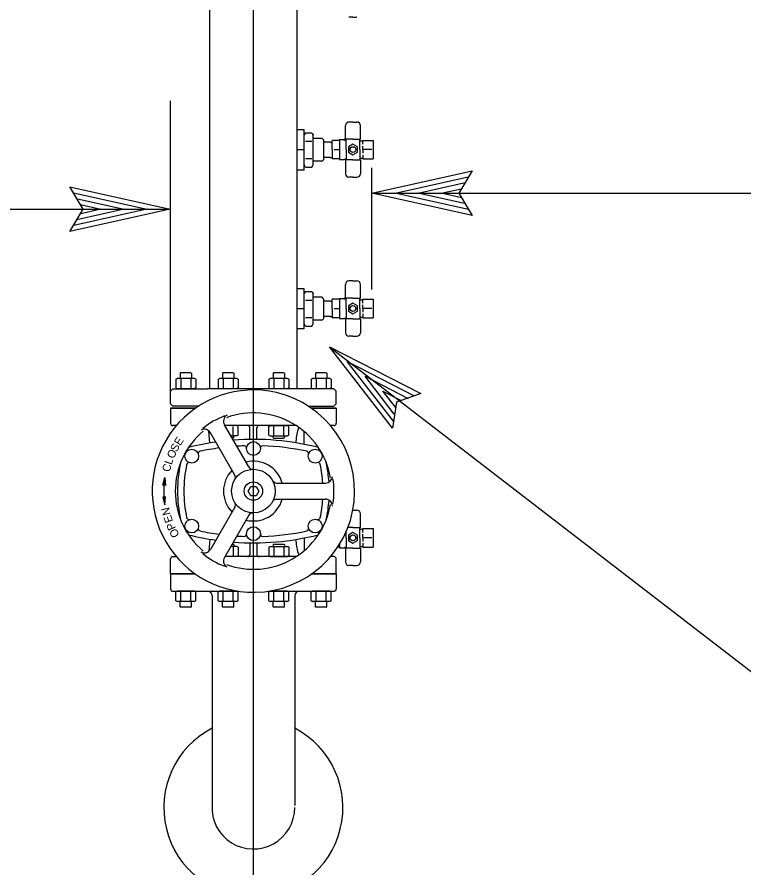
# Model space of a CAD drawing. Extents: x -1680 to 1155, y -802 to 799.
# Drawn here: x 469.8 to 513.3, y -472.5 to -421.5 of the extents above; entities that cross this region are included whole.
import ezdxf

# ---------------------------------------------------------------- set-up
doc = ezdxf.new("R2010")
doc.units = 0
doc.layers.add('Misc CnstDet(22)', color=7, linetype='Continuous')

msp = doc.modelspace()

# ---------------------------------------------------------------- linework, layer by layer
at = {"layer": 'Misc CnstDet(22)'}
for p, q in [((483.911, -491.28), (483.911, -367.568)), ((481.299, -443.793), (481.299, -415.653)), ((486.531, -443.793), (486.531, -415.653)), ((489.873, -421.544), (489.634, -421.544)), ((489.873, -421.544), (490.113, -421.544)), ((478.959, -444.309), (478.959, -426.565)), ((486.944, -428.293), (486.531, -428.293)), ((486.944, -430.702), (486.944, -428.293)), ((489.427, -428.86), (489.427, -428.034)), ((489.873, -427.828), (489.634, -427.828)), ((489.873, -427.828), (490.113, -427.828)), ((490.319, -428.86), (490.319, -428.034)), ((487.024, -428.469), (486.944, -428.608)), ((487.024, -428.469), (487.414, -428.469)), ((487.414, -428.469), (487.494, -428.608)), ((487.457, -428.534), (487.494, -428.599)), ((487.494, -430.388), (487.494, -428.599)), ((487.494, -430.388), (487.494, -428.599)), ((488.029, -428.805), (487.494, -428.806)), ((488.138, -428.915), (488.029, -428.805)), ((487.026, -428.977), (487.412, -428.977)), ((488.138, -430.071), (488.138, -428.915)), ((488.242, -429.031), (488.138, -429.034)), ((488.517, -429.031), (488.242, -429.031)), ((488.517, -429.031), (488.62, -429.034)), ((488.621, -429.48), (488.621, -428.929)), ((489.072, -428.929), (488.621, -428.929)), ((488.676, -429.084), (488.676, -429.084)), ((489.072, -428.929), (489.002, -428.929)), ((489.072, -428.879), (489.072, -430.08)), ((489.072, -428.879), (489.348, -428.879)), ((489.372, -428.879), (489.372, -428.879)), ((489.372, -428.929), (489.372, -428.896)), ((489.391, -428.905), (489.46, -428.905)), ((489.873, -428.86), (489.427, -428.86)), ((489.46, -429.48), (489.46, -428.86)), ((489.873, -428.86), (490.319, -428.86)), ((490.286, -429.48), (490.286, -428.86)), ((490.291, -428.963), (490.449, -428.963)), ((490.466, -429.154), (490.466, -428.929)), ((490.466, -428.929), (491.075, -428.929)), ((490.466, -429.48), (490.466, -429.267)), ((491.075, -428.929), (491.075, -429.48)), ((486.944, -429.498), (486.531, -429.498)), ((488.621, -429.48), (488.621, -430.03)), ((488.746, -429.48), (489.072, -429.48)), ((489.46, -429.48), (489.46, -430.099)), ((490.286, -429.48), (490.286, -430.099)), ((490.466, -429.48), (490.466, -429.693)), ((490.466, -429.805), (490.466, -430.03)), ((491.011, -429.48), (490.53, -429.48)), ((491.075, -429.48), (491.075, -430.03)), ((487.026, -430.01), (487.412, -430.01)), ((488.029, -430.181), (487.494, -430.181)), ((488.138, -430.071), (488.029, -430.181)), ((488.242, -429.956), (488.138, -429.953)), ((488.517, -429.956), (488.242, -429.956)), ((488.517, -429.956), (488.62, -429.953)), ((489.072, -430.03), (488.621, -430.03)), ((488.676, -430.009), (488.676, -430.009)), ((489.072, -430.08), (489.348, -430.08)), ((489.372, -430.03), (489.372, -430.063)), ((489.391, -430.054), (489.46, -430.054)), ((489.427, -430.099), (489.427, -430.925)), ((489.873, -430.099), (489.427, -430.099)), ((489.873, -430.099), (490.319, -430.099)), ((490.291, -429.996), (490.449, -429.996)), ((490.319, -430.099), (490.319, -430.925)), ((490.466, -430.03), (491.075, -430.03)), ((486.944, -430.702), (486.531, -430.702)), ((487.024, -430.526), (486.944, -430.388)), ((487.024, -430.526), (487.414, -430.526)), ((487.414, -430.526), (487.494, -430.388)), ((490.999, -437.861), (490.999, -430.566)), ((490.999, -432.082), (496.999, -430.752)), ((496.999, -430.752), (496.199, -432.082)), ((496.999, -430.752), (496.999, -430.752)), ((489.873, -431.132), (489.634, -431.132)), ((489.873, -431.132), (490.113, -431.132)), ((492.39, -432.079), (496.764, -431.112)), ((473.733, -433.05), (472.933, -431.71)), ((472.933, -431.71), (472.933, -431.71)), ((472.933, -431.71), (478.933, -433.05)), ((493.762, -432.085), (496.587, -431.458)), ((495.143, -432.086), (496.352, -431.818)), ((473.149, -432.066), (477.553, -433.049)), ((496.999, -433.422), (490.999, -432.082)), ((490.999, -432.082), (490.999, -432.082)), ((490.999, -432.082), (565.927, -432.083)), ((496.783, -433.067), (492.379, -432.083)), ((496.549, -432.707), (493.762, -432.085)), ((496.373, -432.36), (495.143, -432.086)), ((496.199, -432.082), (496.999, -433.422)), ((473.383, -432.425), (476.17, -433.048)), ((473.559, -432.772), (474.788, -433.047)), ((415.24, -433.05), (478.933, -433.05)), ((478.933, -433.05), (472.932, -434.38)), ((472.933, -434.38), (473.733, -433.05)), ((477.542, -433.053), (473.167, -434.021)), ((476.17, -433.048), (473.345, -433.674)), ((474.788, -433.047), (473.58, -433.315)), ((478.933, -433.05), (478.933, -433.05)), ((496.999, -433.422), (496.999, -433.422)), ((472.933, -434.38), (472.933, -434.38)), ((489.873, -437.338), (489.634, -437.338)), ((489.873, -437.338), (490.113, -437.338)), ((486.944, -437.804), (486.531, -437.804)), ((486.944, -440.213), (486.944, -437.804)), ((487.024, -437.979), (486.944, -438.118)), ((487.024, -437.979), (487.414, -437.979)), ((487.414, -437.979), (487.494, -438.118)), ((489.427, -438.371), (489.427, -437.545)), ((490.319, -438.371), (490.319, -437.545)), ((487.026, -438.487), (487.412, -438.487)), ((487.457, -438.045), (487.494, -438.109)), ((487.494, -439.898), (487.494, -438.109)), ((487.494, -439.898), (487.494, -438.109)), ((488.029, -438.316), (487.494, -438.316)), ((488.138, -438.425), (488.029, -438.316)), ((488.138, -439.582), (488.138, -438.425)), ((488.621, -438.99), (488.621, -438.439)), ((489.072, -438.439), (488.621, -438.439)), ((489.072, -438.439), (489.002, -438.439)), ((489.072, -438.389), (489.072, -439.591)), ((489.072, -438.389), (489.348, -438.389)), ((489.372, -438.389), (489.372, -438.389)), ((489.372, -438.439), (489.372, -438.406)), ((489.391, -438.415), (489.46, -438.415)), ((489.873, -438.371), (489.427, -438.371)), ((489.46, -438.99), (489.46, -438.371)), ((489.873, -438.371), (490.319, -438.371)), ((490.286, -438.99), (490.286, -438.371)), ((490.291, -438.474), (490.449, -438.474)), ((490.466, -438.665), (490.466, -438.439)), ((490.466, -438.439), (491.075, -438.439)), ((491.075, -438.439), (491.075, -438.99)), ((486.944, -439.008), (486.531, -439.008)), ((488.242, -438.541), (488.138, -438.544)), ((488.517, -438.541), (488.242, -438.541)), ((488.517, -438.541), (488.62, -438.544)), ((488.621, -438.99), (488.621, -439.541)), ((488.676, -438.594), (488.676, -438.594)), ((488.746, -438.99), (489.072, -438.99)), ((489.46, -438.99), (489.46, -439.61)), ((490.286, -438.99), (490.286, -439.61)), ((490.466, -438.99), (490.466, -438.777)), ((490.466, -438.99), (490.466, -439.203)), ((491.011, -438.99), (490.53, -438.99)), ((491.075, -438.99), (491.075, -439.541)), ((487.026, -439.52), (487.412, -439.52)), ((488.242, -439.466), (488.138, -439.463)), ((488.517, -439.466), (488.242, -439.466)), ((488.517, -439.466), (488.62, -439.463)), ((488.676, -439.519), (488.676, -439.519)), ((490.291, -439.506), (490.449, -439.506)), ((490.466, -439.315), (490.466, -439.541)), ((487.024, -440.037), (486.944, -439.898)), ((487.024, -440.037), (487.414, -440.037)), ((487.414, -440.037), (487.494, -439.898)), ((488.029, -439.691), (487.494, -439.691)), ((488.138, -439.582), (488.029, -439.691)), ((489.072, -439.541), (488.621, -439.541)), ((489.072, -439.591), (489.348, -439.591)), ((489.372, -439.541), (489.372, -439.574)), ((489.391, -439.565), (489.46, -439.565)), ((489.427, -439.61), (489.427, -440.436)), ((489.873, -439.61), (489.427, -439.61)), ((489.873, -439.61), (490.319, -439.61)), ((490.319, -439.61), (490.319, -440.436)), ((490.466, -439.541), (491.075, -439.541)), ((486.944, -440.213), (486.531, -440.213)), ((489.873, -440.642), (489.634, -440.642)), ((489.873, -440.642), (490.113, -440.642)), ((492.235, -446.142), (488.465, -441.286)), ((488.465, -441.286), (488.465, -441.286)), ((488.465, -441.286), (493.936, -444.085)), ((492.295, -445.73), (489.528, -442.166)), ((489.539, -442.17), (493.526, -444.212)), ((479.555, -442.83), (479.522, -442.863)), ((479.522, -442.863), (479.522, -443.176)), ((480.177, -442.83), (479.555, -442.83)), ((480.177, -442.83), (480.21, -442.863)), ((480.21, -442.863), (480.21, -443.176)), ((482.088, -442.83), (482.055, -442.863)), ((482.055, -442.863), (482.055, -443.176)), ((482.71, -442.83), (482.088, -442.83)), ((482.71, -442.83), (482.743, -442.863)), ((482.743, -442.863), (482.743, -443.176)), ((485.12, -442.83), (485.087, -442.863)), ((485.087, -442.863), (485.087, -443.176)), ((485.742, -442.83), (485.12, -442.83)), ((485.742, -442.83), (485.775, -442.863)), ((485.775, -442.863), (485.775, -443.176)), ((487.653, -442.83), (487.62, -442.863)), ((487.62, -442.863), (487.62, -443.176)), ((488.275, -442.83), (487.653, -442.83)), ((488.275, -442.83), (488.308, -442.863)), ((488.308, -442.863), (488.308, -443.176)), ((492.344, -445.304), (490.593, -443.048)), ((490.593, -443.048), (493.169, -444.366)), ((479.27, -443.223), (479.35, -443.176)), ((479.27, -443.223), (479.27, -443.747)), ((480.382, -443.176), (479.35, -443.176)), ((479.568, -443.224), (479.568, -443.746)), ((480.164, -443.224), (480.164, -443.746)), ((480.462, -443.223), (480.382, -443.176)), ((480.462, -443.223), (480.462, -443.747)), ((481.803, -443.223), (481.883, -443.176)), ((481.803, -443.223), (481.803, -443.747)), ((482.915, -443.176), (481.883, -443.176)), ((482.101, -443.224), (482.101, -443.746)), ((482.697, -443.224), (482.697, -443.746)), ((482.995, -443.223), (482.915, -443.176)), ((482.995, -443.223), (482.995, -443.747)), ((484.835, -443.223), (484.915, -443.176)), ((484.835, -443.223), (484.835, -443.747)), ((485.947, -443.176), (484.915, -443.176)), ((485.133, -443.224), (485.133, -443.746)), ((485.729, -443.224), (485.729, -443.746)), ((486.027, -443.223), (485.947, -443.176)), ((486.027, -443.223), (486.027, -443.747)), ((487.368, -443.223), (487.448, -443.176)), ((487.368, -443.223), (487.368, -443.747)), ((488.48, -443.176), (487.448, -443.176)), ((487.666, -443.224), (487.666, -443.746)), ((488.262, -443.224), (488.262, -443.746)), ((488.56, -443.223), (488.48, -443.176)), ((488.56, -443.223), (488.56, -443.747)), ((478.959, -443.931), (479.097, -443.793)), ((478.959, -444.688), (478.959, -443.931)), ((479.097, -443.793), (481.162, -443.793)), ((479.27, -443.747), (479.35, -443.793)), ((480.382, -443.793), (479.35, -443.793)), ((480.462, -443.747), (480.382, -443.793)), ((488.733, -443.793), (481.162, -443.793)), ((481.803, -443.747), (481.883, -443.793)), ((482.915, -443.793), (481.883, -443.793)), ((482.995, -443.747), (482.915, -443.793)), ((484.835, -443.747), (484.915, -443.793)), ((485.947, -443.793), (484.915, -443.793)), ((486.027, -443.747), (485.947, -443.793)), ((487.368, -443.747), (487.448, -443.793)), ((488.48, -443.793), (487.448, -443.793)), ((488.56, -443.747), (488.48, -443.793)), ((488.871, -443.931), (488.733, -443.793)), ((488.871, -444.688), (488.871, -443.931)), ((492.429, -444.924), (491.656, -443.929)), ((491.656, -443.929), (492.759, -444.493)), ((493.936, -444.085), (492.472, -444.6)), ((493.936, -444.085), (493.936, -444.085)), ((492.472, -444.6), (492.235, -446.142)), ((478.959, -444.688), (479.097, -444.826)), ((480.432, -444.963), (478.959, -444.963)), ((478.959, -444.963), (478.959, -445.858)), ((478.959, -444.963), (480.432, -444.963)), ((478.959, -444.963), (480.432, -444.963)), ((480.637, -444.826), (479.097, -444.826)), ((487.193, -444.826), (488.733, -444.826)), ((488.871, -444.963), (487.398, -444.963)), ((487.398, -444.963), (488.871, -444.963)), ((487.398, -444.963), (488.871, -444.963)), ((488.733, -444.826), (488.871, -444.688)), ((488.871, -444.963), (488.871, -445.858)), ((479.3, -445.996), (479.097, -445.996)), ((483.637, -448.474), (482.176, -445.943)), ((486.467, -445.996), (482.206, -445.996)), ((482.915, -445.996), (482.206, -445.996)), ((482.697, -446.565), (482.697, -446.043)), ((482.995, -446.042), (482.915, -445.996)), ((482.995, -446.566), (482.995, -446.042)), ((483.709, -446.823), (483.709, -446.133)), ((484.122, -446.823), (484.122, -446.133)), ((484.835, -446.042), (484.915, -445.996)), ((484.835, -446.566), (484.835, -446.042)), ((484.915, -445.996), (485.947, -445.996)), ((485.133, -446.565), (485.133, -446.043)), ((485.729, -446.565), (485.729, -446.043)), ((486.027, -446.042), (485.947, -445.996)), ((486.027, -446.566), (486.027, -446.042)), ((488.733, -445.996), (488.53, -445.996)), ((492.235, -446.142), (492.235, -446.142)), ((481.304, -447.04), (481.253, -446.318)), ((482.803, -448.956), (481.341, -446.425)), ((482.915, -446.612), (482.562, -446.612)), ((482.743, -446.717), (482.743, -446.612)), ((482.995, -446.566), (482.915, -446.612)), ((484.835, -446.566), (484.915, -446.612)), ((484.915, -446.612), (485.947, -446.612)), ((485.087, -446.717), (485.087, -446.612)), ((485.775, -446.717), (485.775, -446.612)), ((486.027, -446.566), (485.947, -446.612)), ((486.944, -447.115), (486.944, -446.35)), ((482.743, -446.717), (482.623, -446.717)), ((482.71, -446.75), (482.743, -446.717)), ((485.12, -446.75), (485.087, -446.717)), ((485.12, -446.75), (485.742, -446.75)), ((485.742, -446.75), (485.775, -446.717)), ((485.305, -449.437), (488.228, -449.437)), ((485.305, -450.401), (488.228, -450.401)), ((482.803, -450.882), (481.341, -453.414)), ((489.873, -451.062), (489.863, -451.062)), ((489.873, -451.062), (490.113, -451.062)), ((483.637, -451.364), (482.176, -453.895)), ((490.319, -452.095), (490.319, -451.269)), ((489.873, -452.095), (489.568, -452.095)), ((489.873, -452.095), (490.319, -452.095)), ((490.286, -452.714), (490.286, -452.095)), ((490.291, -452.198), (490.449, -452.198)), ((490.466, -452.389), (490.466, -452.164)), ((490.466, -452.164), (491.075, -452.164)), ((491.075, -452.164), (491.075, -452.714)), ((486.944, -452.723), (486.944, -453.488)), ((489.46, -452.714), (489.46, -452.356)), ((489.46, -452.714), (489.46, -453.334)), ((490.286, -452.714), (490.286, -453.334)), ((490.466, -452.714), (490.466, -452.501)), ((490.466, -452.714), (490.466, -452.927)), ((491.011, -452.714), (490.53, -452.714)), ((491.075, -452.714), (491.075, -453.265)), ((481.304, -452.799), (481.253, -453.52)), ((482.915, -453.226), (482.562, -453.226)), ((482.743, -453.121), (482.623, -453.121)), ((482.697, -453.273), (482.697, -453.795)), ((482.743, -453.121), (482.743, -453.226)), ((482.995, -453.272), (482.915, -453.226)), ((482.995, -453.272), (482.995, -453.796)), ((483.709, -453.015), (483.709, -453.705)), ((484.122, -453.015), (484.122, -453.705)), ((484.835, -453.272), (484.915, -453.226)), ((484.835, -453.272), (484.835, -453.796)), ((484.915, -453.226), (485.947, -453.226)), ((485.12, -453.088), (485.087, -453.121)), ((485.087, -453.121), (485.087, -453.226)), ((485.12, -453.088), (485.742, -453.088)), ((485.133, -453.273), (485.133, -453.795)), ((485.729, -453.273), (485.729, -453.795)), ((485.742, -453.088), (485.775, -453.121)), ((485.775, -453.121), (485.775, -453.226)), ((486.027, -453.272), (485.947, -453.226)), ((486.027, -453.272), (486.027, -453.796)), ((489.072, -453.265), (488.964, -453.265)), ((489.072, -453.096), (489.072, -453.315)), ((489.372, -453.265), (489.372, -453.298)), ((490.291, -453.231), (490.449, -453.231)), ((490.466, -453.04), (490.466, -453.265)), ((490.466, -453.265), (491.075, -453.265)), ((489.072, -453.315), (489.348, -453.315)), ((489.391, -453.289), (489.46, -453.289)), ((489.427, -453.334), (489.427, -454.16)), ((489.873, -453.334), (489.427, -453.334)), ((489.873, -453.334), (490.319, -453.334)), ((490.319, -453.334), (490.319, -454.16)), ((478.959, -454.875), (478.959, -453.98)), ((478.959, -454.617), (478.959, -453.98)), ((479.097, -453.842), (479.3, -453.842)), ((479.27, -453.842), (479.27, -453.807)), ((486.467, -453.842), (482.206, -453.842)), ((482.915, -453.842), (482.206, -453.842)), ((482.995, -453.796), (482.915, -453.842)), ((484.835, -453.796), (484.915, -453.842)), ((484.915, -453.842), (485.947, -453.842)), ((486.027, -453.796), (485.947, -453.842)), ((488.733, -453.842), (488.53, -453.842)), ((488.56, -453.842), (488.56, -453.807)), ((488.871, -454.875), (488.871, -453.98)), ((489.873, -454.366), (489.634, -454.366)), ((489.873, -454.366), (490.113, -454.366)), ((480.432, -454.875), (478.959, -454.875)), ((478.959, -454.875), (480.432, -454.875)), ((478.959, -454.875), (478.959, -455.77)), ((487.398, -454.875), (488.871, -454.875)), ((488.871, -454.875), (487.398, -454.875)), ((488.871, -454.875), (488.871, -455.77)), ((479.097, -455.907), (483.004, -455.907)), ((479.27, -455.953), (479.35, -455.907)), ((479.27, -456.478), (479.27, -455.953)), ((480.382, -455.907), (479.35, -455.907)), ((479.568, -456.477), (479.568, -455.955)), ((480.164, -456.477), (480.164, -455.955)), ((480.462, -455.953), (480.382, -455.907)), ((480.462, -456.478), (480.462, -455.953)), ((481.437, -456.183), (481.437, -468.728)), ((481.803, -455.953), (481.883, -455.907)), ((481.803, -456.478), (481.803, -455.953)), ((482.915, -455.907), (481.883, -455.907)), ((482.101, -456.477), (482.101, -455.955)), ((482.697, -456.477), (482.697, -455.955)), ((482.995, -455.953), (482.915, -455.907)), ((482.995, -456.478), (482.995, -455.953)), ((484.826, -455.907), (488.733, -455.907)), ((484.835, -455.953), (484.915, -455.907)), ((484.835, -456.478), (484.835, -455.953)), ((485.947, -455.907), (484.915, -455.907)), ((485.133, -456.477), (485.133, -455.955)), ((485.729, -456.477), (485.729, -455.955)), ((486.027, -455.953), (485.947, -455.907)), ((486.027, -456.478), (486.027, -455.953)), ((486.393, -456.183), (486.393, -468.728)), ((487.368, -455.953), (487.448, -455.907)), ((487.368, -456.478), (487.368, -455.953)), ((488.48, -455.907), (487.448, -455.907)), ((487.666, -456.477), (487.666, -455.955)), ((488.262, -456.477), (488.262, -455.955)), ((488.56, -455.953), (488.48, -455.907)), ((488.56, -456.478), (488.56, -455.953)), ((479.27, -456.478), (479.35, -456.524)), ((480.382, -456.524), (479.35, -456.524)), ((479.522, -456.838), (479.522, -456.524)), ((479.555, -456.871), (479.522, -456.838)), ((480.177, -456.871), (480.21, -456.838)), ((480.21, -456.838), (480.21, -456.524)), ((480.462, -456.478), (480.382, -456.524)), ((481.803, -456.478), (481.883, -456.524)), ((482.915, -456.524), (481.883, -456.524)), ((482.055, -456.838), (482.055, -456.524)), ((482.088, -456.871), (482.055, -456.838)), ((482.71, -456.871), (482.743, -456.838)), ((482.743, -456.838), (482.743, -456.524)), ((482.995, -456.478), (482.915, -456.524)), ((484.835, -456.478), (484.915, -456.524)), ((485.947, -456.524), (484.915, -456.524)), ((485.087, -456.838), (485.087, -456.524)), ((485.12, -456.871), (485.087, -456.838)), ((485.742, -456.871), (485.775, -456.838)), ((485.775, -456.838), (485.775, -456.524)), ((486.027, -456.478), (485.947, -456.524)), ((487.368, -456.478), (487.448, -456.524)), ((488.48, -456.524), (487.448, -456.524)), ((487.62, -456.838), (487.62, -456.524)), ((487.653, -456.871), (487.62, -456.838)), ((488.275, -456.871), (488.308, -456.838)), ((488.308, -456.838), (488.308, -456.524)), ((488.56, -456.478), (488.48, -456.524)), ((480.177, -456.871), (479.555, -456.871)), ((482.71, -456.871), (482.088, -456.871)), ((485.742, -456.871), (485.12, -456.871)), ((488.275, -456.871), (487.653, -456.871))]:
    msp.add_line(p, q, dxfattribs=at)
for points in [[(489.598, -429.639), (489.873, -429.798), (490.149, -429.639), (490.149, -429.321), (489.873, -429.162), (489.598, -429.321)], [(489.598, -439.149), (489.873, -439.308), (490.149, -439.149), (490.149, -438.831), (489.873, -438.672), (489.598, -438.831)], [(478.651, -449.575), (478.496, -449.563), (478.608, -449.106)], [(483.756, -450.194), (483.597, -449.919), (483.756, -449.644), (484.074, -449.644), (484.233, -449.919), (484.074, -450.194)], [(478.651, -450.263), (478.496, -450.275), (478.608, -450.732)], [(489.598, -452.873), (489.873, -453.032), (490.149, -452.873), (490.149, -452.555), (489.873, -452.396), (489.598, -452.555)]]:
    msp.add_lwpolyline(points, close=True, dxfattribs=at)
msp.add_lwpolyline([(488.465, -441.286), (633.132, -552.688), (618.879, -552.688)], dxfattribs=at)
for centre, radius in [((489.873, -429.48), 0.172), ((489.873, -438.99), 0.172), ((483.915, -447.372), 0.413), ((480.22, -447.828), 0.413), ((487.61, -447.828), 0.413), ((483.915, -449.919), 1.308), ((483.915, -449.919), 0.551), ((480.22, -452.01), 0.413), ((487.61, -452.01), 0.413), ((483.915, -452.466), 0.413), ((489.873, -452.714), 0.172)]:
    msp.add_circle(centre, radius, dxfattribs=at)
for centre, radius, start, end in [((489.634, -428.034), 0.206, 90, 180), ((490.113, -428.034), 0.206, 0, 90), ((489.348, -428.903), 0.024, 27.2796, 90), ((489.391, -428.881), 0.024, 207.2796, 270), ((490.291, -428.946), 0.0172, 254.1733, 270), ((490.449, -428.946), 0.0172, 270, 0), ((489.348, -430.056), 0.024, 270, 332.7204), ((489.391, -430.078), 0.024, 90, 152.7204), ((490.449, -430.013), 0.0172, 0, 90), ((489.634, -430.925), 0.206, 180, 270), ((490.113, -430.925), 0.206, 270, 0), ((489.634, -437.545), 0.206, 90, 180), ((490.113, -437.545), 0.206, 0, 90), ((489.348, -438.413), 0.024, 27.2796, 90), ((489.391, -438.391), 0.024, 207.2796, 270), ((490.291, -438.457), 0.0172, 254.1733, 270), ((490.449, -438.457), 0.0172, 270, 0), ((490.449, -439.524), 0.0172, 0, 90), ((489.348, -439.567), 0.024, 270, 332.7204), ((489.391, -439.589), 0.024, 90, 152.7204), ((489.634, -440.436), 0.206, 180, 270), ((490.113, -440.436), 0.206, 270, 0), ((483.915, -449.919), 6.057, 76.8634, 270.7347), ((483.915, -449.919), 6.057, 270.9106, 76.8634), ((483.915, -449.919), 4.818, 110.954, 128.8267), ((482.533, -445.736), 0.413, 118.6865, 210), ((483.915, -449.919), 4.68, 9.8969, 110.1031), ((479.097, -445.858), 0.138, 180, 270), ((483.571, -446.133), 0.138, 0, 90), ((484.259, -446.133), 0.138, 90, 180), ((487.04, -446.353), 0.474, 148.9584, 162.6862), ((488.733, -445.858), 0.138, 270, 0), ((483.915, -449.919), 4.68, 129.8969, 230.1031), ((480.983, -446.631), 0.413, 30, 118.2085), ((491.788, -447.565), 5.374, 165.4239, 174.2397), ((483.915, -462.584), 15.762, 98.2117, 104.2666), ((483.915, -462.584), 15.762, 75.7334, 94.3855), ((480.748, -447.671), 0.138, 101.9908, 196.6074), ((483.915, -462.584), 15.384, 97.6469, 101.9908), ((483.915, -462.584), 15.384, 92.0678, 93.7076), ((483.365, -447.348), 0.138, 357.4512, 92.0678), ((484.465, -447.348), 0.138, 87.9322, 182.5489), ((483.915, -462.584), 15.384, 78.0092, 87.9322), ((487.082, -447.671), 0.138, 343.3926, 78.0092), ((483.915, -449.919), 1.79, 15.6185, 104.3815), ((487.431, -449.919), 8.059, 167.8489, 192.1511), ((487.431, -449.919), 7.68, 168.0139, 180), ((480.053, -448.353), 0.138, 72.3405, 168.0139), ((483.915, -449.919), 1.79, 135.6185, 224.3815), ((483.876, -448.336), 0.275, 210, 271.4281), ((487.777, -448.353), 0.138, 11.9861, 107.6595), ((480.399, -449.919), 7.68, 3.5967, 11.9861), ((480.399, -449.919), 8.059, 3.9315, 12.1511), ((482.564, -449.094), 0.275, 328.5719, 30), ((488.228, -449.024), 0.413, 270, 358.2085), ((483.915, -449.919), 4.818, 350.954, 8.8267), ((483.915, -449.919), 5.369, 173.2861, 186.7139), ((485.305, -449.162), 0.275, 208.5719, 270), ((487.431, -449.919), 7.68, 180, 191.9861), ((483.915, -449.919), 4.68, 249.8969, 350.1031), ((482.564, -450.745), 0.275, 330, 31.4281), ((483.915, -449.919), 1.79, 255.6185, 344.3815), ((485.305, -450.676), 0.275, 90, 151.4281), ((480.399, -449.919), 7.68, 348.0139, 356.4033), ((488.228, -450.814), 0.413, 358.6865, 90), ((480.399, -449.919), 8.059, 347.8489, 356.0685), ((483.876, -451.502), 0.275, 88.5719, 150), ((490.113, -451.269), 0.206, 0, 90), ((480.053, -451.485), 0.138, 191.9861, 287.6595), ((487.777, -451.485), 0.138, 252.3405, 348.0139), ((480.748, -452.168), 0.138, 163.3926, 258.0092), ((487.082, -452.168), 0.138, 281.9908, 16.6074), ((490.291, -452.181), 0.0172, 254.1733, 270), ((490.449, -452.181), 0.0172, 270, 0), ((483.915, -437.254), 15.762, 255.7334, 261.7884), ((483.915, -437.254), 15.384, 258.0092, 262.3531), ((483.915, -437.254), 15.762, 265.6145, 284.2666), ((483.915, -437.254), 15.384, 266.2924, 267.9322), ((483.365, -452.49), 0.138, 267.9322, 2.5489), ((484.465, -452.49), 0.138, 177.4512, 272.0678), ((483.915, -437.254), 15.384, 272.0678, 281.9908), ((491.788, -452.273), 5.374, 185.7603, 194.5761), ((490.449, -453.248), 0.0172, 0, 90), ((480.983, -453.207), 0.413, 238.6865, 330), ((483.915, -449.919), 4.818, 230.954, 248.8267), ((483.571, -453.705), 0.138, 270, 0), ((484.259, -453.705), 0.138, 180, 270), ((487.04, -453.485), 0.474, 197.3138, 211.0416), ((489.348, -453.291), 0.024, 270, 332.7204), ((489.391, -453.313), 0.024, 90, 152.7204), ((479.097, -453.98), 0.138, 90, 180), ((482.533, -454.102), 0.413, 150, 238.2085), ((488.733, -453.98), 0.138, 0, 90), ((489.634, -454.16), 0.206, 180, 270), ((490.113, -454.16), 0.206, 270, 0), ((478.821, -454.617), 0.138, 348.2317, 0), ((479.097, -455.77), 0.138, 180, 270), ((488.733, -455.77), 0.138, 270, 0), ((481.162, -456.183), 0.275, 0, 90), ((486.668, -456.183), 0.275, 90, 180), ((488.733, -455.77), 0.138, 270, 320.9284), ((483.911, -468.861), 5.358, 117.5041, 62.4289), ((483.911, -468.861), 2.478, 176.9128, 359.9994)]:
    msp.add_arc(centre, radius, start, end, dxfattribs=at)

# ---------------------------------------------------------------- texts
for s, rotation, p in [('E', 57.3232, (479.535, -447.236)), ('S', 62.0107, (479.329, -447.61)), ('O', 66.6982, (479.15, -448.011)), ('L', 71.3857, (479.02, -448.374)), ('C', 76.0732, (478.906, -448.802)), ('N', 104.3391, (478.971, -451.301)), ('E', 109.3391, (479.112, -451.718)), ('P', 114.3391, (479.291, -452.135)), ('O', 119.3391, (479.508, -452.542))]:
    msp.add_text(s, height=0.482, rotation=rotation, dxfattribs=at).set_placement(p)

doc.saveas('drawing.dxf')
